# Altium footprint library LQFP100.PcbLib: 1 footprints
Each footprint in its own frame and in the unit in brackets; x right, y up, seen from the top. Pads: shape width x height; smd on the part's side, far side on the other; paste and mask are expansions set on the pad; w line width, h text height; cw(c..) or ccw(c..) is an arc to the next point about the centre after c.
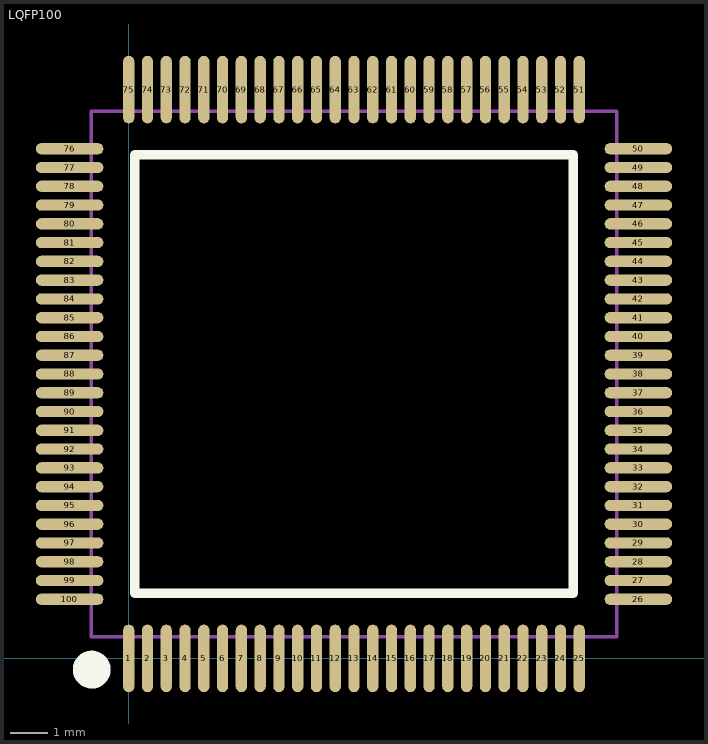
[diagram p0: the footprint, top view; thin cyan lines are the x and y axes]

## LQFP100 [mm]
pads (100):
  oval 0.3x1.8 smd: 1(0,0) 2(0.5,0) 3(1,0) 4(1.5,0) 5(2,0) 6(2.5,0) 7(3,0) 8(3.5,0) 9(4,0) 10(4.5,0) 11(5,0) 12(5.5,0) 13(6,0) 14(6.5,0) 15(7,0) 16(7.5,0) 17(8,0) 18(8.5,0) 19(9,0) 20(9.5,0) 21(10,0) 22(10.5,0) 23(11,0) 24(11.5,0) 25(12,0) 51(12,15.151) 52(11.5,15.151) 53(11,15.151) 54(10.5,15.151) 55(10,15.151) 56(9.5,15.151) 57(9,15.151) 58(8.5,15.151) 59(8,15.151) 60(7.5,15.151) 61(7,15.151) 62(6.5,15.151) 63(6,15.151) 64(5.5,15.151) 65(5,15.151) 66(4.5,15.151) 67(4,15.151) 68(3.5,15.151) 69(3,15.151) 70(2.5,15.151) 71(2,15.151) 72(1.5,15.151) 73(1,15.151) 74(0.5,15.151) 75(0,15.151)
  oval 1.8x0.3 smd: 26(13.575,1.575) 27(13.575,2.075) 28(13.575,2.575) 29(13.575,3.075) 30(13.575,3.575) 31(13.575,4.075) 32(13.575,4.575) 33(13.575,5.075) 34(13.575,5.575) 35(13.575,6.075) 36(13.575,6.575) 37(13.575,7.075) 38(13.575,7.575) 39(13.575,8.075) 40(13.575,8.575) 41(13.575,9.075) 42(13.575,9.575) 43(13.575,10.075) 44(13.575,10.575) 45(13.575,11.075) 46(13.575,11.575) 47(13.575,12.075) 48(13.575,12.575) 49(13.575,13.075) 50(13.575,13.575) 76(-1.575,13.575) 77(-1.575,13.075) 78(-1.575,12.575) 79(-1.575,12.075) 80(-1.575,11.575) 81(-1.575,11.075) 82(-1.575,10.575) 83(-1.575,10.075) 84(-1.575,9.575) 85(-1.575,9.075) 86(-1.575,8.575) 87(-1.575,8.075) 88(-1.575,7.575) 89(-1.575,7.075) 90(-1.575,6.575) 91(-1.575,6.075) 92(-1.575,5.575) 93(-1.575,5.075) 94(-1.575,4.575) 95(-1.575,4.075) 96(-1.575,3.575) 97(-1.575,3.075) 98(-1.575,2.575) 99(-1.575,2.075) 100(-1.575,1.575)
Top Overlay:
  circle w0.508: c-0.985,-0.299 r0.25
  lines w0.254: 0.158,1.733 0.158,13.417 11.842,13.417 11.842,1.733 0.158,1.733
Mechanical 13:
  lines w0.1: -1,0.575 13,0.575 13,14.575 -1,14.575 -1,0.575
3D body "LQFP100-14x14.STEP": height 1.45, standoff 0, extent -2.003,-0.427 14.003,15.578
